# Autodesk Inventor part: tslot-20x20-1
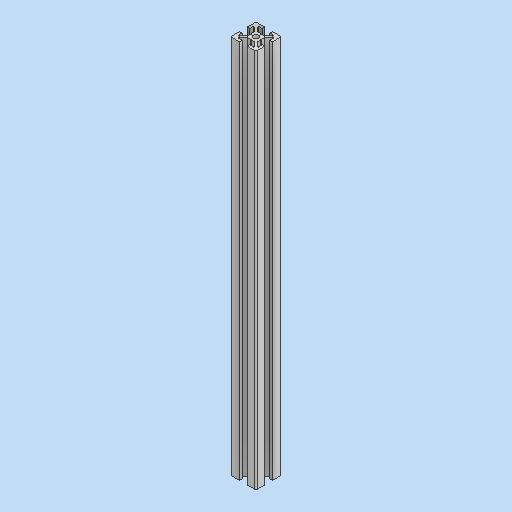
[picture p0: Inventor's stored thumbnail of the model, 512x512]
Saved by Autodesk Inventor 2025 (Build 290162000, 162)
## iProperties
Created: 2025-03
Part Number: tslot-20x20-1
Material: Generico
Document SubType Name: Modeling
Designer: Ryzen5700u
Density: 1 g/cm^3
Appearance: Default
Author: Ryzen5700u
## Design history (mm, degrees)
feature "Base1"
sketch "Schizzo1"
  geometry: L1 (3.761, -16)-(4.7, -16) reference; L2 (3.761, -16)-(0.7, -12.939) reference; L3 (0.7, -12.939)-(0.7, -10.52) reference; L4 (0.4, -10)-(0.7, -10.52) reference; L5 (0.4, -10)-(0.7, -9.48) reference; L6 (0.7, -7.061)-(0.7, -9.48) reference; L7 (3.761, -4)-(0.7, -7.061) reference; L8 (3.761, -4)-(4.7, -4) reference; L9 (4.7, -4)-(4.7, -7) reference; L10 (4.7, -7)-(6.4, -7) reference; L11 (6.7, -6.7)-(6.7, -1) reference; L12 (5.7, 0)-(0, 0) reference; L13 (-0.3, -2)-(-0.3, -0.3) reference; L14 (2.7, -2)-(-0.3, -2) reference; L15 (2.7, -2.939)-(2.7, -2) reference; L16 (2.7, -2.939)-(-0.361, -6) reference; L17 (-0.361, -6)-(-2.78, -6) reference; L18 (-3.3, -6.3)-(-2.78, -6) reference; L19 (-3.3, -6.3)-(-3.82, -6) reference; L20 (-6.239, -6)-(-3.82, -6) reference; L21 (-9.3, -2.939)-(-6.239, -6) reference; L22 (-9.3, -2.939)-(-9.3, -2) reference; L23 (-9.3, -2)-(-6.3, -2) reference; L24 (-6.3, -2)-(-6.3, -0.3) reference; L25 (-12.3, 0)-(-6.6, 0) reference; L26 (-13.3, -6.7)-(-13.3, -1) reference; L27 (-11.3, -7)-(-13, -7) reference; L28 (-11.3, -4)-(-11.3, -7) reference; L29 (-10.361, -4)-(-11.3, -4) reference; L30 (-10.361, -4)-(-7.3, -7.061) reference; L31 (-7.3, -7.061)-(-7.3, -9.48) reference; L32 (-7, -10)-(-7.3, -9.48) reference; L33 (-7, -10)-(-7.3, -10.52) reference; L34 (-7.3, -12.939)-(-7.3, -10.52) reference; L35 (-10.361, -16)-(-7.3, -12.939) reference; L36 (-10.361, -16)-(-11.3, -16) reference; L37 (-11.3, -16)-(-11.3, -13) reference; L38 (-11.3, -13)-(-13, -13) reference; L39 (-13.3, -13.3)-(-13.3, -19) reference; L40 (-12.3, -20)-(-6.6, -20) reference; L41 (-6.3, -18)-(-6.3, -19.7) reference; L42 (-9.3, -18)-(-6.3, -18) reference; L43 (-9.3, -17.061)-(-9.3, -18) reference; L44 (-9.3, -17.061)-(-6.239, -14) reference; L45 (-6.239, -14)-(-3.82, -14) reference; L46 (-3.3, -13.7)-(-3.82, -14) reference; L47 (-3.3, -13.7)-(-2.78, -14) reference; L48 (-0.361, -14)-(-2.78, -14) reference; L49 (2.7, -17.061)-(-0.361, -14) reference; L50 (2.7, -17.061)-(2.7, -18) reference; L51 (2.7, -18)-(-0.3, -18) reference; L52 (-0.3, -18)-(-0.3, -19.7) reference; L53 (5.7, -20)-(0, -20) reference; L54 (6.7, -13.3)-(6.7, -19) reference; L55 (4.7, -13)-(6.4, -13) reference; L56 (4.7, -16)-(4.7, -13) reference; C1 r 2.1 at (-3.3, -10) reference; A1 r 0.3 centre (6.4, -6.7) between (6.4, -7) and (6.7, -6.7) reference; A2 r 1 centre (5.7, -1) between (6.7, -1) and (5.7, 0) reference; A3 r 0.3 centre (0, -0.3) between (0, 0) and (-0.3, -0.3) reference; A4 r 0.3 centre (-6.6, -0.3) between (-6.3, -0.3) and (-6.6, 0) reference; A5 r 1 centre (-12.3, -1) between (-12.3, 0) and (-13.3, -1) reference; A6 r 0.3 centre (-13, -6.7) between (-13.3, -6.7) and (-13, -7) reference; A7 r 0.3 centre (-13, -13.3) between (-13, -13) and (-13.3, -13.3) reference; A8 r 1 centre (-12.3, -19) between (-13.3, -19) and (-12.3, -20) reference; A9 r 0.3 centre (-6.6, -19.7) between (-6.6, -20) and (-6.3, -19.7) reference; A10 r 0.3 centre (0, -19.7) between (-0.3, -19.7) and (0, -20) reference; A11 r 1 centre (5.7, -19) between (5.7, -20) and (6.7, -19) reference; A12 r 0.3 centre (6.4, -13.3) between (6.7, -13.3) and (6.4, -13) reference; 1 further point
extrude "Estrusione1" join sketch "Schizzo1" distance "d0" = 290; taper "d1" = 0 deg
node "Solido1"
node "Linea chiusa proiettata1"
